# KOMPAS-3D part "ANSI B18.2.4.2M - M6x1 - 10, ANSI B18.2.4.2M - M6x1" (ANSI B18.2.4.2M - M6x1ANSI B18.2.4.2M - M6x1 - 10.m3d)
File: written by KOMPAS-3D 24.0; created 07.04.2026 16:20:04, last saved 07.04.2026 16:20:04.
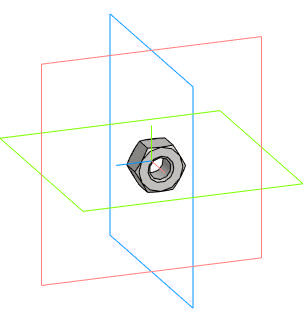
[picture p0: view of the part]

Document properties: Автор: Main; Полное имя файла: D:\DN.ru Аутсерс\Стекло смотровое DN.ru\Исходники\Стекло смотровое DN.ru SG2-34G-F тип В ГОСТ 21836-2021 Ду40 Ру40, углеродистая сталь, фланцевое\ANSI B18.2.4.2M - M6x1ANSI B18.2.4.2M - M6x1 - 10.m3d

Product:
- Body: Solid1  | qty 1
- Part/product: ANSI B18.2.4.2M - M6x1 - 10  | designation ANSI B18.2.4.2M - M6x1
    Комментарий: Типы метрических   шестигранных гаек   2
    additional columns: Сталь, мягкая

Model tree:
1. Solid1  (labels: Solid1)

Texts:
  ANSI B18.2.4.2M - M6x1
